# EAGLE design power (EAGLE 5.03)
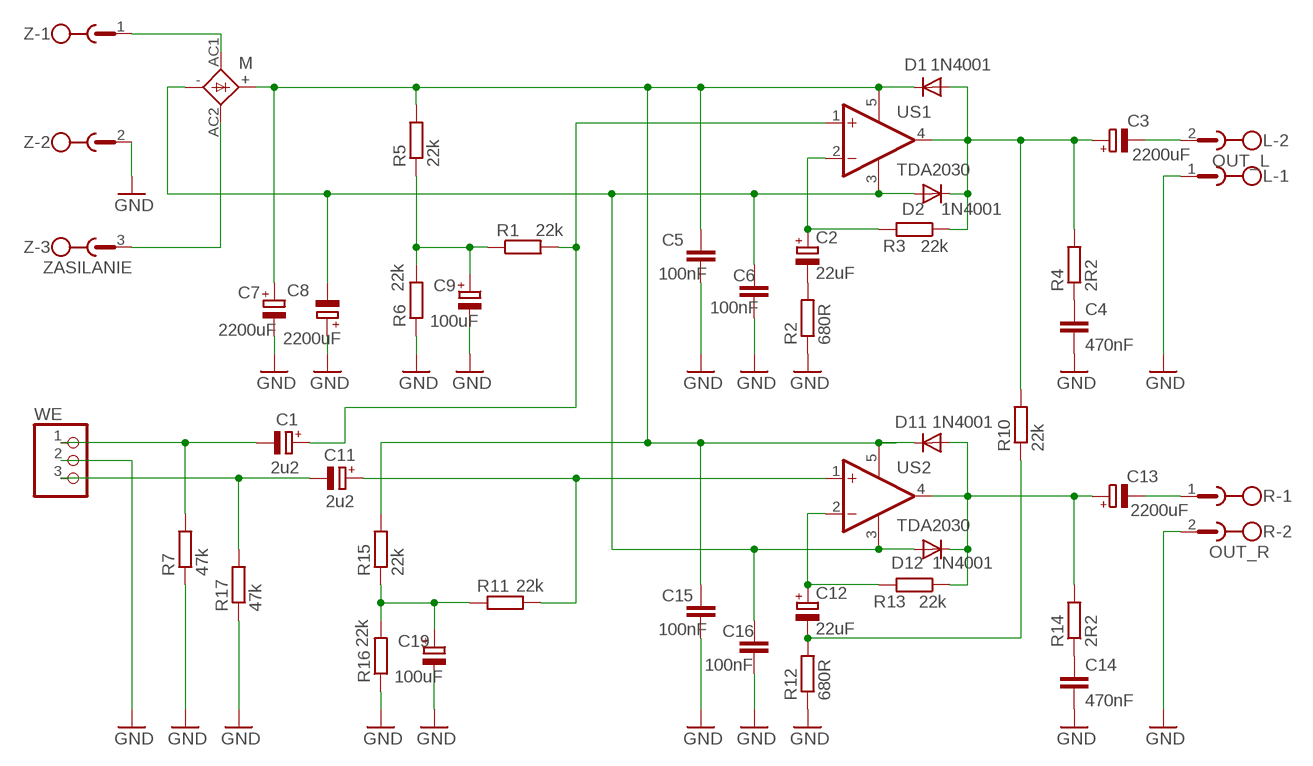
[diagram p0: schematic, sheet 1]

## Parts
C1  2u2  CPOL-EUE2.5-7  [E2,5-7]
C2  22uF  CPOL-EUE2.5-7  [E2,5-7]
C3  2200uF  CPOL-EUE7.5-16  [E7,5-16]
C4  470nF  C-EU050-030X075  [C050-030X075]
C5  100nF  C-EU050-030X075  [C050-030X075]
C6  100nF  C-EU050-030X075  [C050-030X075]
C7  2200uF  CPOL-EUE7.5-16  [E7,5-16]
C8  2200uF  CPOL-EUE7.5-16  [E7,5-16]
C9  100uF  CPOL-EUE2.5-7  [E2,5-7]
C11  2u2  CPOL-EUE2.5-7  [E2,5-7]
C12  22uF  CPOL-EUE2.5-7  [E2,5-7]
C13  2200uF  CPOL-EUE7.5-16  [E7,5-16]
C14  470nF  C-EU050-030X075  [C050-030X075]
C15  100nF  C-EU050-030X075  [C050-030X075]
C16  100nF  C-EU050-030X075  [C050-030X075]
C19  100uF  CPOL-EUE2.5-7  [E2,5-7]
D1  1N4001  1N4148DO35-10  [DO35-10]
D2  1N4001  1N4148DO35-10  [DO35-10]
D11  1N4001  1N4148DO35-10  [DO35-10]
D12  1N4001  1N4148DO35-10  [DO35-10]
L  OUT_L  MSTBV2  [MSTBV2]
M  KBU  [KBU]
R  OUT_R  MSTBV2  [MSTBV2]
R1  22k  R-EU_0207/10  [0207/10]
R2  680R  R-EU_0207/10  [0207/10]
R3  22k  R-EU_0207/15  [0207/15]
R4  2R2  R-EU_0207/10  [0207/10]
R5  22k  R-EU_0207/10  [0207/10]
R6  22k  R-EU_0207/10  [0207/10]
R7  47k  R-EU_0207/10  [0207/10]
R10  22k  R-EU_0207/12  [0207/12]
R11  22k  R-EU_0207/10  [0207/10]
R12  680R  R-EU_0207/10  [0207/10]
R13  22k  R-EU_0207/15  [0207/15]
R14  2R2  R-EU_0207/10  [0207/10]
R15  22k  R-EU_0207/10  [0207/10]
R16  22k  R-EU_0207/10  [0207/10]
R17  47k  R-EU_0207/10  [0207/10]
US1  TDA2030  TDA2030V  [CB360]
US2  TDA2030  TDA2030V  [CB360]
WE  PINHD-1X3  [1X03]
Z  ZASILANIE  MSTBV3  [MSTBV3]

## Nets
GND: C4.2 C5.2 C6.2 C7.- C8.+ C9.- C14.2 C15.2 C16.2 C19.- L.1 R2.1 R6.1 R7.1 R12.1 R16.1 R17.1 R.2 WE.2 Z.2
N$1: C1.- R7.2 WE.1
N$2: C1.+ R1.2 US1.1(+IN)
N$3: C11.- R17.2 WE.3
N$4: C3.- L.2
N$5: C19.+ R11.1 R15.1 R16.2
N$7: M.AC1 Z.1
N$8: C2.+ R3.2 US1.2(-IN)
N$9: C12.- R10.1 R12.2
N$10: C3.+ D1.A D2.C R3.1 R4.2 R10.2 US1.4(OUT)
N$11: C11.+ R11.2 US2.1(+IN)
N$12: C4.1 R4.1
N$13: C2.- R2.2
N$14: M.AC2 Z.3
N$15: C5.1 C7.+ C15.1 D1.C D11.C M.+ R5.2 R15.2 US1.5(V+) US2.5(V+)
N$16: C12.+ R13.2 US2.2(-IN)
N$17: C13.+ D11.A D12.C R13.1 R14.2 US2.4(OUT)
N$18: C14.1 R14.1
N$21: C13.- R.1
N$22: C6.1 C8.- C16.1 D2.A D12.A M.- US1.3(GND) US2.3(GND)
N$24: C9.+ R1.1 R5.1 R6.2

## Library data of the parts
C1-C3 C7-C9 C11-C13 C19 = rcl:CPOL-EU: POLARIZED CAPACITOR, European symbol
C4-C6 C14-C16 = rcl:C-EU: CAPACITOR, European symbol
D1 D2 D11 D12 = diode:1N4148: DIODE
L R = con-phoenix-508:MSTBV2: PHOENIX
M = rectifier:KBU: DIOTEC RECTIFIER
R1-R7 R10-R17 = rcl:R-EU_: RESISTOR, European symbol
US1 US2 = linear:TDA2030: Power OP AMP
WE = pinhead:PINHD-1X3: PIN HEADER
Z = con-phoenix-508:MSTBV3: PHOENIX

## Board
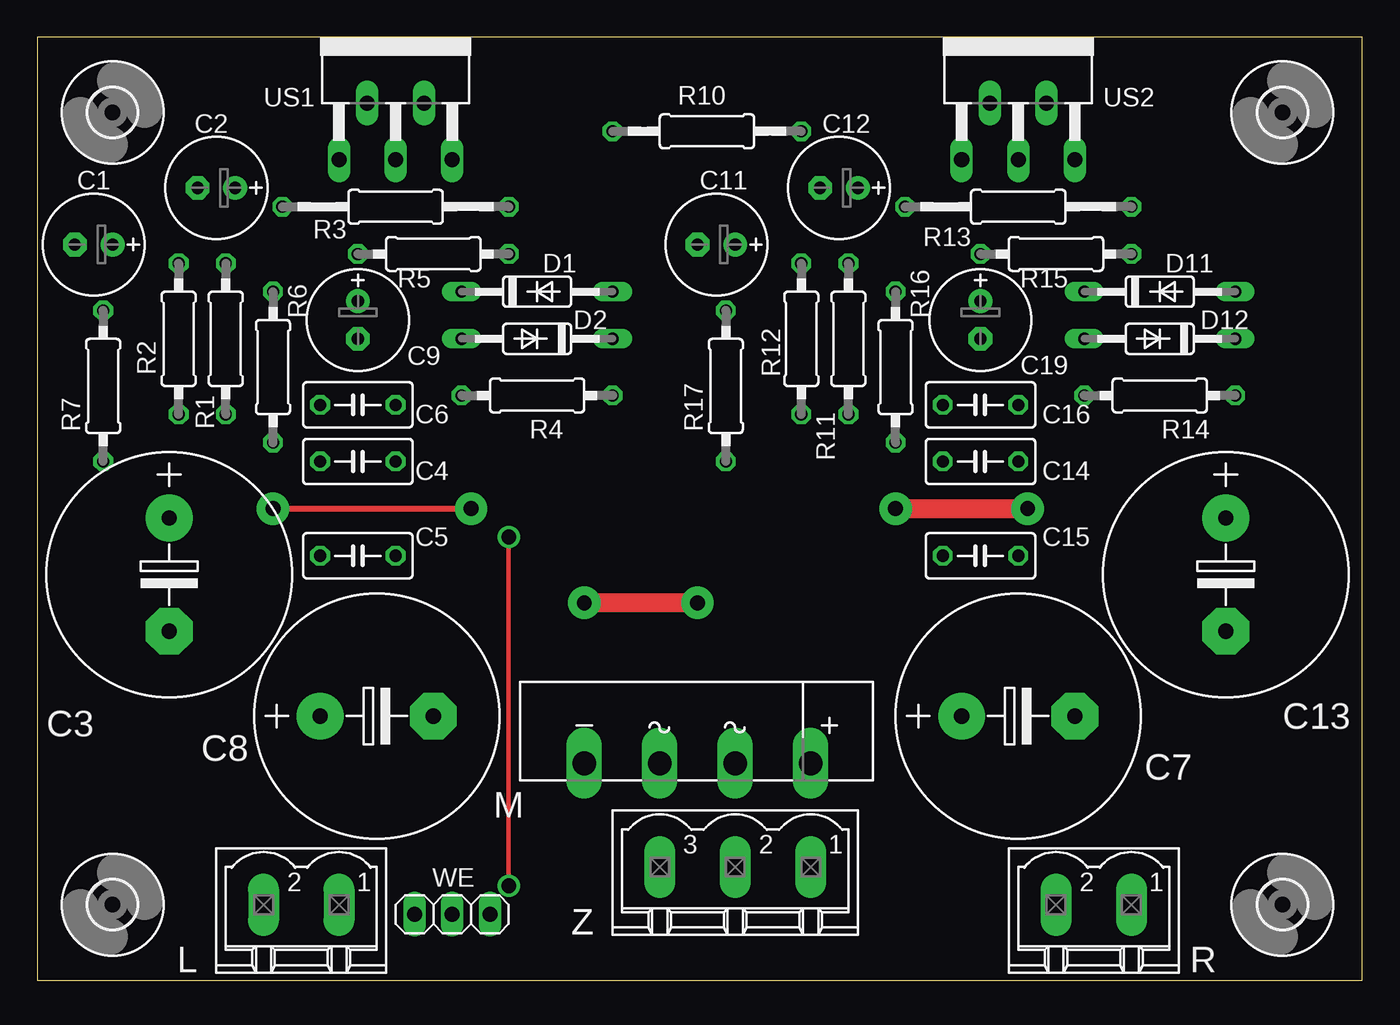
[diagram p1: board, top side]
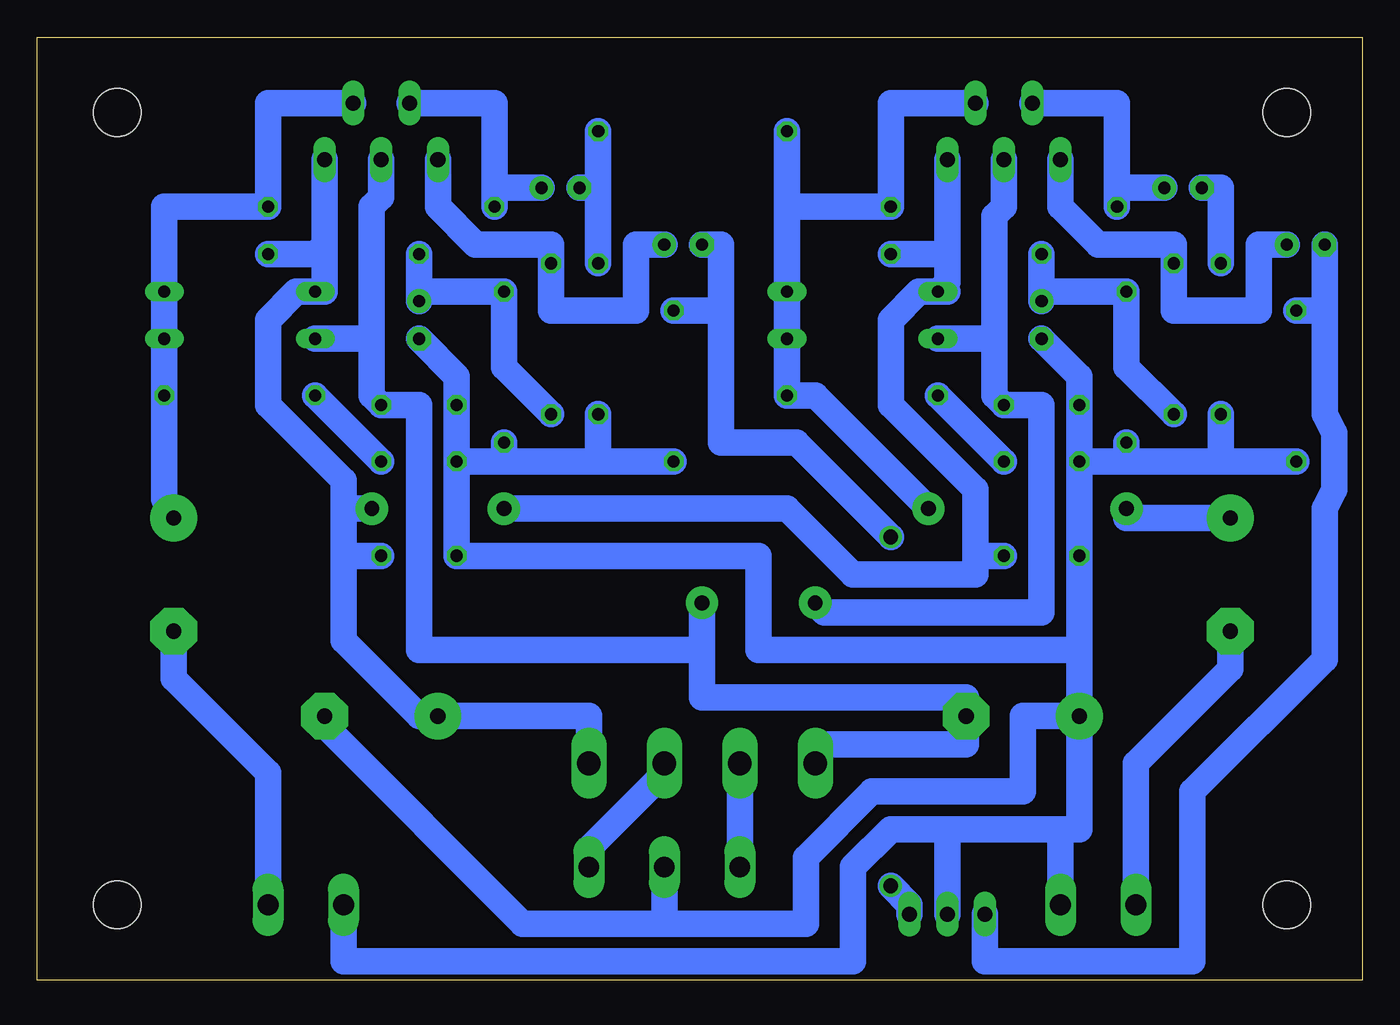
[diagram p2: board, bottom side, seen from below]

Size 89.2 x 63.49 mm. Coordinates in mm from the lower left corner, seen from the top.
Outline: 0,0 89.2,0 89.2,63.49 0,63.49 0,0
Copper layers (1*16): Top 0.035mm / dielectric 1.5mm / Bottom 0.035mm
Design rules "default": minimum track width 10mil, minimum drill 24mil, track to track 8mil, track to pad 8mil, pad to pad 8mil, via to via 8mil, smd to smd 8mil, copper to edge 40mil, drill to drill 8mil, minimum pad ring 10mil, minimum via ring 8mil, stop-mask expansion 4mil, vias tented up to drill 0mil, thermal gap 10mil

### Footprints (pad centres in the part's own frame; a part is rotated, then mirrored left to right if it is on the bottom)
E2,5-7 = drill 0.813 pad 1.6 round: + -1.27,0 | drill 0.813 pad 1.6 octagon: - 1.27,0
E7,5-16 = drill 1.016 pad 3.15 round: + -3.81,0 | drill 1.016 pad 3.15 octagon: - 3.81,0
C050-030X075 = drill 0.813 octagon: 1 -2.54,0; 2 2.54,0
DO35-10 = drill 0.813 long: A 5.08,0; C -5.08,0
MSTBV2 = drill 1.397 long: 1 -2.54,0; 2 2.54,0
KBU = drill 1.6 long: + -7.62,2.54; - 7.62,2.54; AC1 -2.54,2.54; AC2 2.54,2.54
0207/10 = drill 0.813 octagon: 1 -5.08,0; 2 5.08,0
0207/15 = drill 0.813 octagon: 1 -7.62,0; 2 7.62,0
0207/12 = drill 0.813 octagon: 1 -6.35,0; 2 6.35,0
3,2 = hole 3.2: 0,0
CB360 = drill 1.016 long: 1 -3.81,-8.255; 2 -1.905,-4.445; 3 0,-8.255; 4 1.905,-4.445; 5 3.81,-8.255
1X03 = drill 1.016 long: 1 -2.54,0; 2 0,0; 3 2.54,0
MSTBV3 = drill 1.397 long: 1 -5.08,0; 2 0,0; 3 5.08,0

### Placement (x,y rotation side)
C1  3.81,49.53 180 top
C2  12.06,53.34 180 top
C3  8.89,27.3 270 top
C4  21.59,34.92 180 top
C5  21.59,28.57 180 top
C6  21.59,38.73 180 top
C7  66.04,17.78 0 top
C8  22.86,17.78 0 top
C9  21.59,44.45 270 top
C11  45.72,49.53 180 top
C12  53.98,53.34 180 top
C13  80.01,27.3 270 top
C14  63.5,34.92 180 top
C15  63.5,28.57 180 top
C16  63.5,38.73 180 top
C19  63.5,44.45 270 top
D1  33.66,46.35 0 top
D2  33.66,43.18 180 top
D11  75.56,46.35 0 top
D12  75.56,43.18 180 top
L  17.78,5.08 180 top
M  44.45,17.14 180 top
R  71.12,5.08 180 top
R1  12.7,43.18 90 top
R2  9.53,43.18 90 top
R3  24.13,52.07 180 top
R4  33.66,39.37 0 top
R5  26.67,48.9 0 top
R6  15.88,41.27 90 top
R7  4.45,40.01 90 top
R10  45.09,57.15 180 top
R11  54.61,43.18 90 top
R12  51.44,43.18 90 top
R13  66.04,52.07 180 top
R14  75.56,39.37 0 top
R15  68.58,48.9 0 top
R16  57.78,41.27 90 top
R17  46.35,40.01 90 top
U$1  [3,2]  5.08,5.08 0 top
U$2  [3,2]  83.82,5.08 0 top
U$3  [3,2]  5.08,58.42 0 top
U$4  [3,2]  83.82,58.42 0 top
US1  24.13,63.5 0 top
US2  66.04,63.5 0 top
WE  27.94,4.45 0 top
Z  46.99,7.62 180 top

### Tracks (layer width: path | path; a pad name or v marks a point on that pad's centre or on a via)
GND
  Bottom 1.778: 15.88,34.92 9.53,34.92 | C9.- 19.05,40.64 C6.2 C4.2 | C4.2 C5.2 19.05,22.23 | 15.88,34.92 R6.1 | C4.2 15.88,34.92 | C19.- 60.96,40.64 C16.2 C14.2 | C14.2 C15.2 40.64,28.57 40.64,22.23 19.05,22.23 | 57.78,34.92 51.44,34.92 | C14.2 60.96,35.56 | C14.2 57.78,34.92 | 57.78,34.92 R16.1 | C8.+ 19.05,10.16 20.32,10.16 | 46.99,3.81 37.47,3.81 37.47,8.26 33.02,12.7 22.86,12.7 22.86,17.78 C8.+ | 46.99,3.81 Z.2 | C7.- 69.85,17.14 56.52,3.81 46.99,3.81 | L.1 20.32,10.16 | R2.1 9.53,34.92 | 9.53,34.92 R7.1 | R12.1 51.44,34.92 | 51.44,34.92 R17.1 | R.2 68.58,1.27 34.29,1.27 34.29,7.62 31.75,10.16 27.94,10.16 | 20.32,10.16 27.94,10.16 | 27.94,10.16 WE.2 | C8.+ 19.05,22.23
N$1
  Bottom 1.778: WE.1 25.4,1.27 11.43,1.27 11.43,12.7 2.54,21.59 2.54,31.75 1.91,33.02 1.91,36.83 2.54,38.1 2.54,45.09 | 2.54,45.09 C1.- | 2.54,45.09 R7.2
N$2
  Bottom 1.778: US1.1 20.32,52.07 17.78,49.53 12.7,49.53 R1.2 12.7,45.09 6.99,45.09 6.99,49.53 C1.+
N$3  (via drill 1)
  Top 0.305: v31.75,6.35 v31.75,29.84
  Bottom 1.778: 43.18,45.09 43.18,49.53 C11.- | 43.18,45.09 43.18,36.2 38.1,36.2 v31.75,29.84 | v31.75,6.35 30.48,5.08 WE.3 | 43.18,45.09 R17.2
N$4
  Bottom 1.778: L.2 15.24,14.61 8.89,20.95 C3.-
N$5
  Bottom 1.778: 63.5,46.35 C19.+ | 63.5,46.35 R15.1 | 63.5,46.35 R16.2 57.78,41.27 R11.1
N$7
  Bottom 1.778: M.AC1 46.99,13.97 52.07,8.89 Z.1
N$8
  Bottom 1.778: US1.2 16.51,59.05 R3.2 16.51,53.34 C2.+
N$9
  Bottom 1.778: R12.2 51.44,53.34 | C12.- 51.44,53.34 | 51.44,53.34 R10.1
N$10  (via drill 1 pad 2.18)
  Top 0.406: v15.88,31.75 v29.21,31.75
  Bottom 1.778: US1.4 31.75,59.05 R3.1 38.73,52.07 | 38.73,52.07 D1.A D2.C R4.2 36.83,39.37 v29.21,31.75 | 38.73,52.07 R10.2 | C3.+ 15.88,31.11 v15.88,31.75
N$11
  Bottom 1.778: C11.+ 48.9,49.53 48.9,45.09 54.61,45.09 R11.2 54.61,49.53 59.69,49.53 62.23,52.07 US2.1
N$12
  Bottom 1.778: C4.1 R4.1
N$13
  Bottom 1.778: R2.2 9.53,53.34 C2.-
N$14
  Bottom 1.778: Z.3 M.AC2
N$15  (via drill 1 pad 2.18)
  Top 1.27: v57.78,31.75 v66.67,31.75
  Bottom 1.778: 27.94,48.9 US1.5 | 27.94,48.9 27.94,46.99 D1.C | 27.94,48.9 R5.2 | D1.C 27.94,46.35 | D1.C 29.84,46.35 31.75,44.45 31.75,38.73 26.04,33.02 26.04,28.57 | 69.85,49.53 69.85,46.35 D11.C 71.75,46.35 73.66,44.45 73.66,38.73 68.58,33.66 68.58,31.75 | 69.85,49.53 US2.5 | R15.2 70.48,48.9 69.85,49.53 | M.+ 52.07,17.78 C7.+ 63.5,17.78 68.58,22.86 68.58,28.57 | v57.78,31.75 38.73,31.75 34.29,27.3 26.04,27.3 26.04,28.57 | C5.1 26.04,28.57 | 68.58,31.75 68.58,28.57 | 68.58,28.57 C15.1 | v66.67,31.75 68.58,31.75
N$16
  Bottom 1.778: C12.+ 58.42,53.34 R13.2 58.42,59.05 US2.2
N$17
  Bottom 1.778: US2.4 73.66,59.05 R13.1 80.64,52.07 D11.A D12.C R14.2 80.64,32.38 C13.+
N$18
  Bottom 1.778: C14.1 R14.1
N$21
  Bottom 1.778: R.1 73.66,13.97 80.01,20.32 C13.-
N$22  (via drill 1 pad 2.18)
  Top 1.27: v44.45,25.4 v36.83,25.4
  Bottom 1.778: US1.3 24.13,52.07 24.77,51.44 24.77,43.18 | 24.77,43.18 24.77,39.37 C6.1 21.59,38.73 21.59,24.77 36.2,24.77 v36.83,25.4 | 24.77,43.18 D2.A | 66.67,43.18 66.67,52.07 66.04,52.7 US2.3 | 66.67,43.18 D12.A | M.- 36.83,15.88 26.67,15.88 C8.- 26.67,19.05 44.45,19.05 44.45,22.23 | 44.45,22.23 63.5,22.23 63.5,38.73 C16.1 66.67,39.37 66.67,43.18 | 44.45,22.23 v44.45,25.4
N$24
  Bottom 1.778: 21.59,46.35 C9.+ | 21.59,46.35 R5.1 | 21.59,46.35 R6.2 15.88,41.27 R1.1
